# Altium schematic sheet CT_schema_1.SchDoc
size 583 x 258 mm
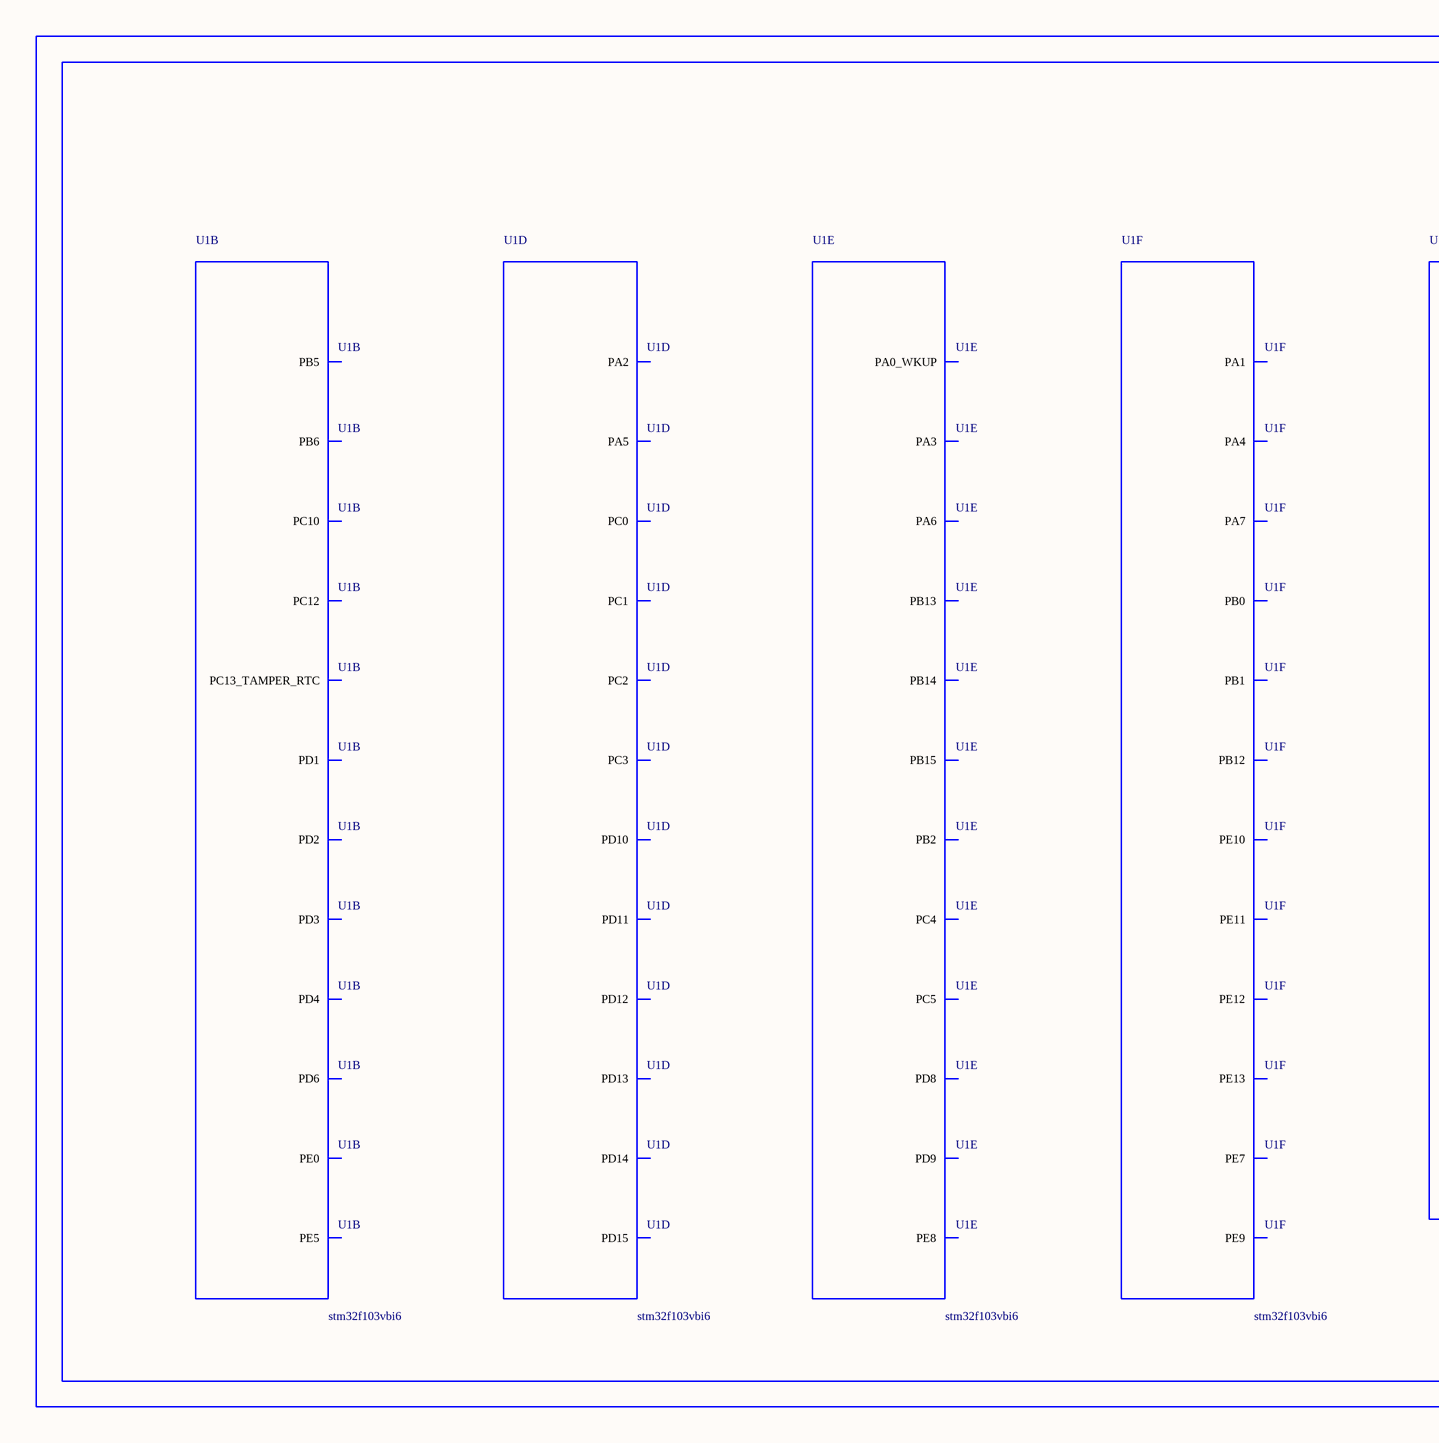
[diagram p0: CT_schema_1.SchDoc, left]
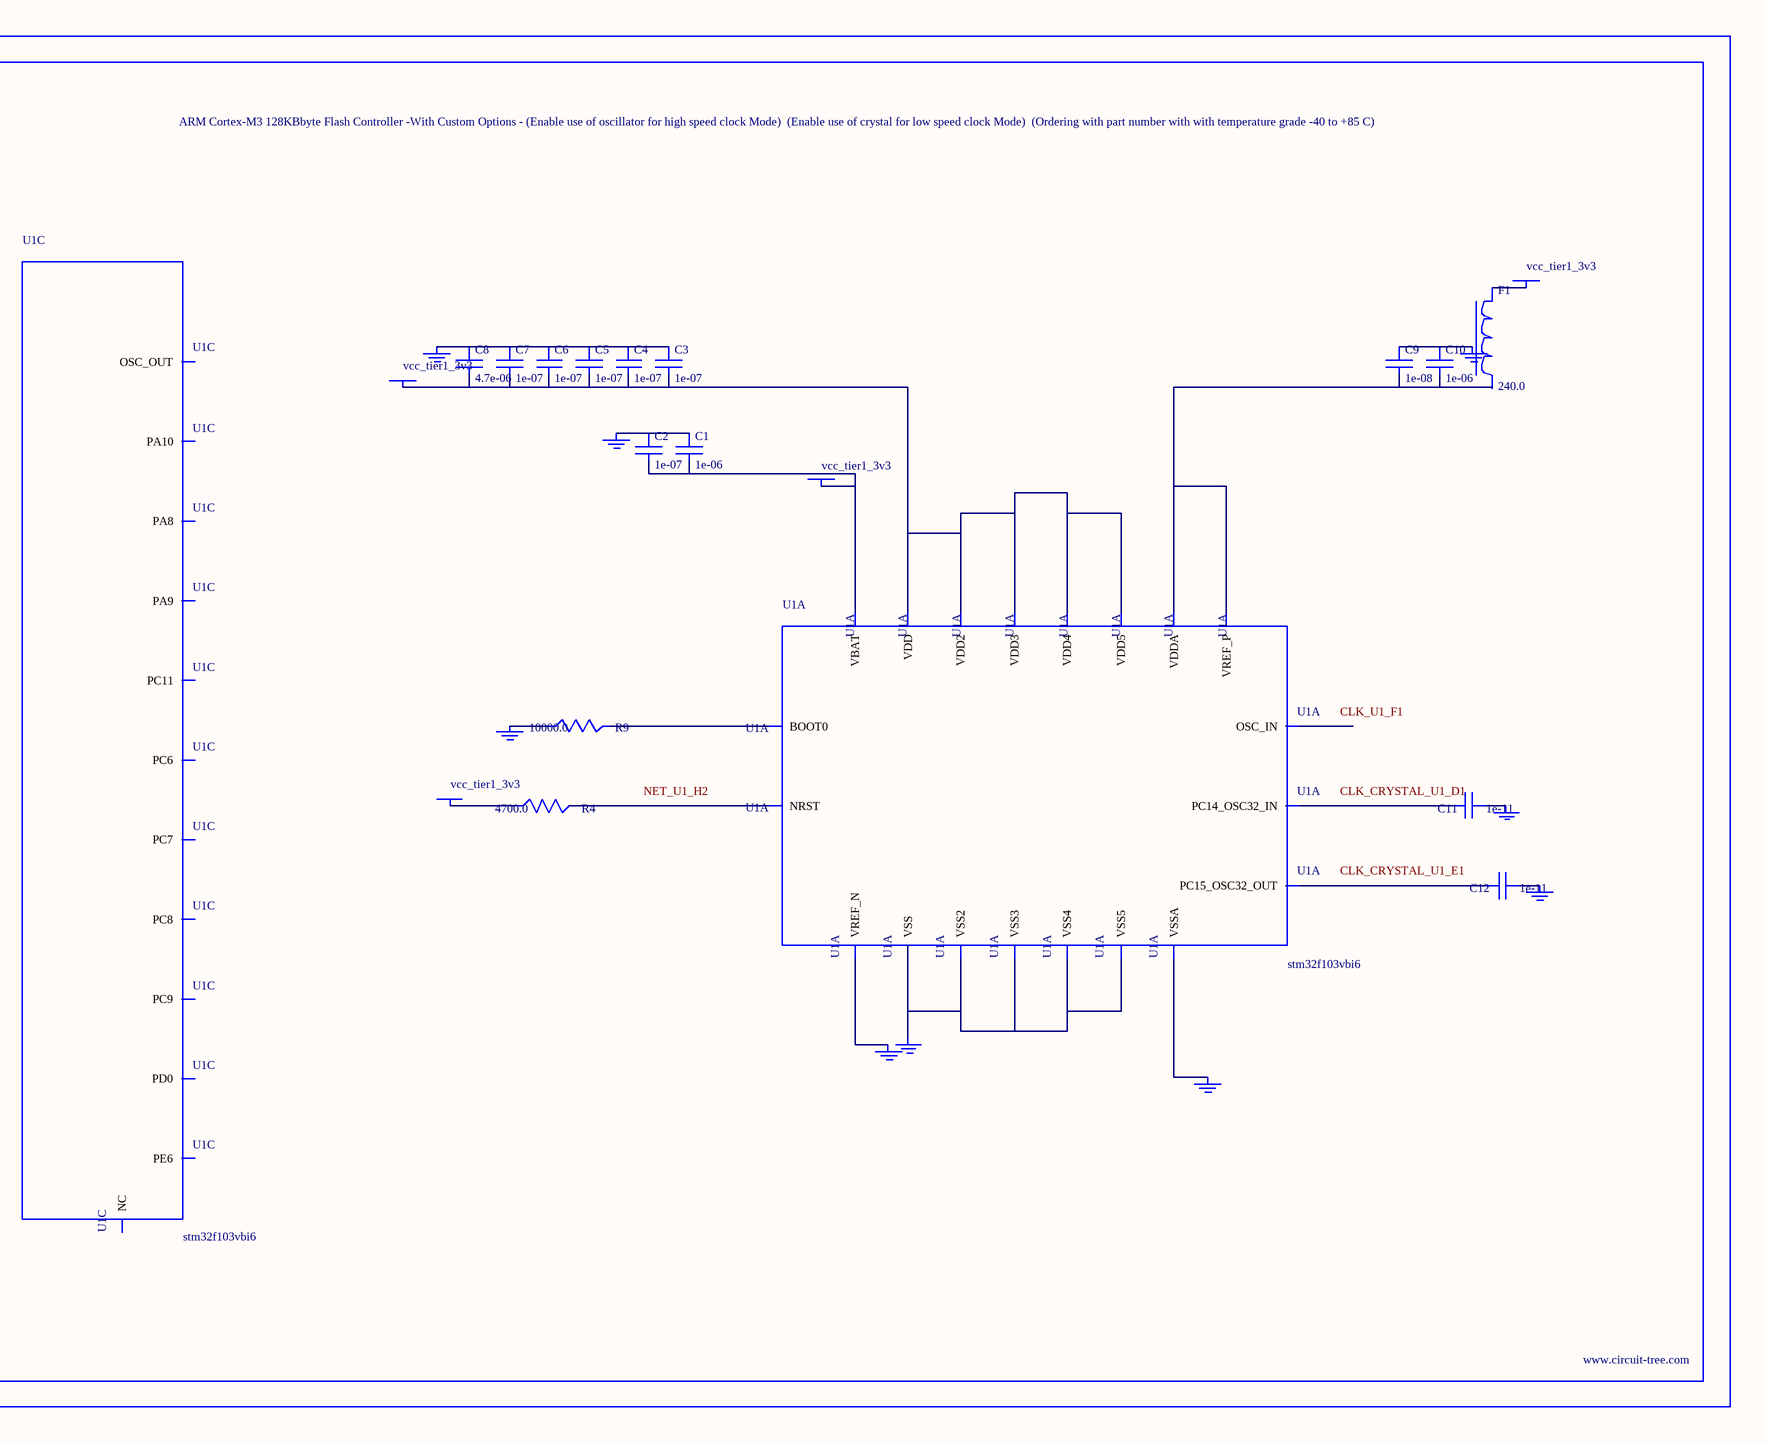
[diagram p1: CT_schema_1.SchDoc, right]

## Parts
BORDER0  (no value)
C1  1e-06  [C0603]
C2  1e-07  [C0603]
C3  1e-07  [C0603]
C4  1e-07  [C0603]
C5  1e-07  [C0603]
C6  1e-07  [C0603]
C7  1e-07  [C0603]
C8  4.7e-06  [C0603]
C9  1e-08  [C0603]
C10  1e-06  [C0603]
C11  1e-11  [C0402]
C12  1e-11  [C0402]
F1  240.0  [L0603]
GND_INSTANCE_0_0  (no value)
GND_INSTANCE_0_1  (no value)
GND_INSTANCE_0_2  (no value)
GND_INSTANCE_0_3  (no value)
GND_INSTANCE_0_4  (no value)
GND_INSTANCE_0_5  (no value)
GND_INSTANCE_0_6  (no value)
GND_INSTANCE_0_7  (no value)
GND_INSTANCE_0_8  (no value)
POWER_INSTANCE_0_0  vcc_tier1_3v3
POWER_INSTANCE_0_1  vcc_tier1_3v3
POWER_INSTANCE_0_2  vcc_tier1_3v3
POWER_INSTANCE_0_3  vcc_tier1_3v3
R4  4700.0  [R0603]
R9  10000.0  [R0603]
U1  stm32f103vbi6  [UFBGA100]  (parts A,B,C,D,E,F of 10)

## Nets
NetC1_1: C1.1 C2.1 GND_INSTANCE_0_0.0(GND)
NetC1_2: C1.2 C2.2 POWER_INSTANCE_0_0.0(PWR) U1.E2(VBAT)
NetC3_1: C3.1 C4.1 C5.1 C6.1 C7.1 C8.1 GND_INSTANCE_0_2.0(GND)
NetC3_2: C3.2 C4.2 C5.2 C6.2 C7.2 C8.2 POWER_INSTANCE_0_2.0(PWR) U1.C4(VDD) U1.G2(VDD4) U1.G11(VDD2) U1.G12(VDD3) U1.H3(VDD5)
NetC9_1: C9.1 C10.1 GND_INSTANCE_0_1.0(GND)
NetC9_2: C9.2 C10.2 U1.L1(VREF_P) U1.M1(VDDA)
NetC11_1: C11.1 GND_INSTANCE_0_4.0(GND)
NetC11_2: C11.2 U1.D1(PC14_OSC32_IN)
NetC12_1: C12.1 GND_INSTANCE_0_5.0(GND)
NetC12_2: C12.2 U1.E1(PC15_OSC32_OUT)
NetF1_1: F1.1 POWER_INSTANCE_0_1.0(PWR)
NetGND_INSTANCE_0_3_0: GND_INSTANCE_0_3.0(GND) R9.1
NetGND_INSTANCE_0_6_0: GND_INSTANCE_0_6.0(GND) U1.J1(VSSA)
NetGND_INSTANCE_0_7_0: GND_INSTANCE_0_7.0(GND) U1.K1(VREF_N)
NetGND_INSTANCE_0_8_0: GND_INSTANCE_0_8.0(GND) U1.D3(VSS) U1.E3(VSS2) U1.F2(VSS5) U1.F11(VSS3) U1.F12(VSS4)
NetPOWER_INSTANCE_0_3_0: POWER_INSTANCE_0_3.0(PWR) R4.1
NetR4_2: R4.2 U1.H2(NRST)
NetR9_2: R9.2 U1.A4(BOOT0)

Not connected (* = marked no-connect by the designer): F1 2; U1 B5(PB6) B6(PD6) B7(PD4) B8(PD3) B9(PD1) B10(PC12) B11(PC10) C1(PC13_TAMPER_RTC) C2(PE5) C3(PE0) C5(PB5) C8(PD2) C9(PD0) C10(PC11) C11(NC) C12(PA10) D2(PE6) D10(PA9) D11(PA8) D12(PC9) E10(PC8) E11(PC7) E12(PC6) F1(OSC_IN) G1(OSC_OUT) H1(PC0) H10(PD15) H11(PD14) H12(PD13) J2(PC1) J3(PC2) J10(PD12) J11(PD11) J12(PD10) K2(PC3) K3(PA2) K4(PA5) K5(PC4) K8(PD9) K9(PD8) K10(PB15) K11(PB14) K12(PB13) L2(PA0_WKUP) L3(PA3) L4(PA6) L5(PC5) L6(PB2) L7(PE8) L8(PE10) L9(PE12) L12(PB12) M2(PA1) M3(PA4) M4(PA7) M5(PB0) M6(PB1) M7(PE7) M8(PE9) M9(PE11) M10(PE13)

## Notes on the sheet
- Labels drawn without touching a wire or pin: CLK_CRYSTAL_U1_D1, CLK_CRYSTAL_U1_E1, CLK_U1_F1, NET_U1_H2

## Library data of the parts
BORDER0 = BORDER_PAGE0
C1 C10 = C0603C105K3RACTU
C2-C7 = 06035C104K4Z2A
C8 = GRM188R6YA475KE15D
C9 = 06035C103K4Z2A
C11 C12 = C0402C100K3GACTU
F1 = Z0603C241ASMST
GND_INSTANCE_0_0-GND_INSTANCE_0_8 = GND
POWER_INSTANCE_0_0-POWER_INSTANCE_0_3 = PWR
R4 = RC0603JR-074K7L
R9 = RC0603JR-0710KL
